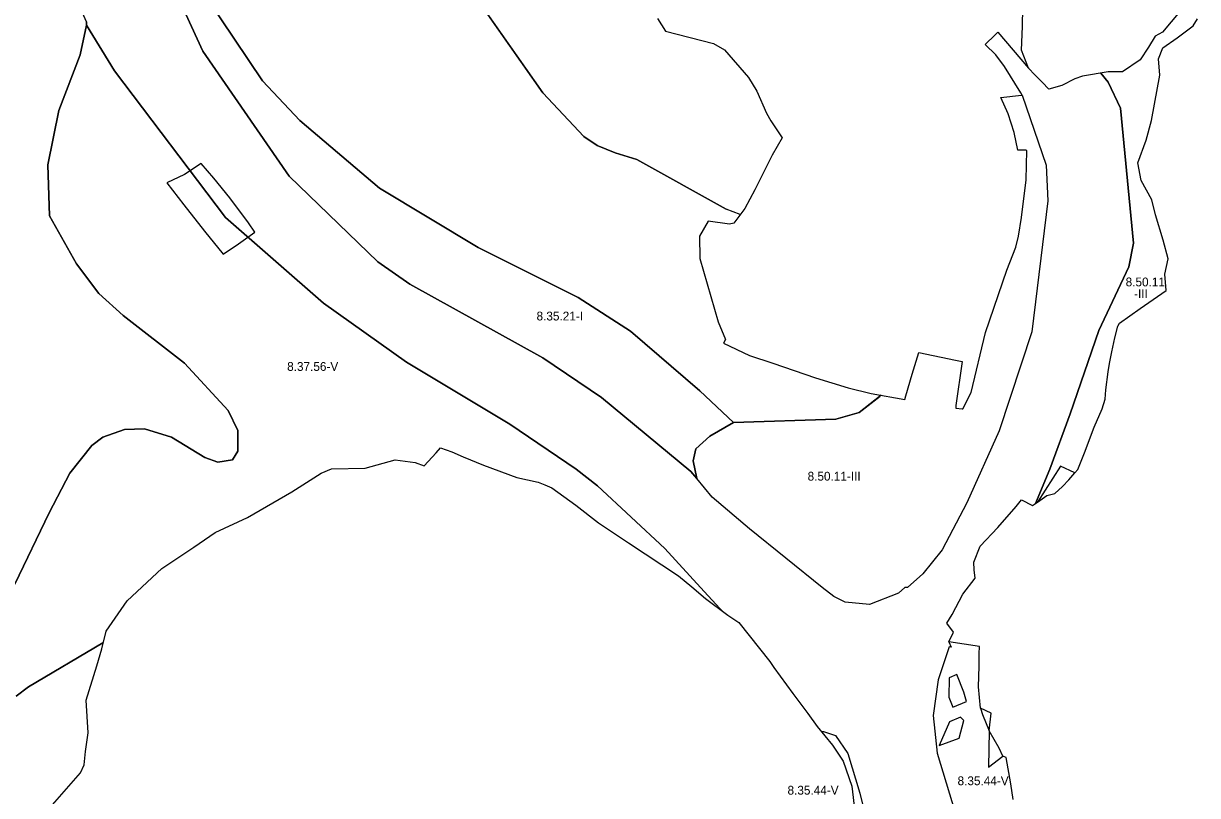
# Model space of a CAD drawing. Extents: x -547623 to -533936, y -1096714 to -1086523.
# Drawn here: x -539983 to -538651, y -1093236 to -1092360 of the extents above; entities that cross this region are included whole.
import ezdxf

# ---------------------------------------------------------------- set-up
doc = ezdxf.new("R2010")
doc.units = 0
for name, color, linetype in [('Vrstva 27', 7, 'Continuous'), ('Vrstva 28', 7, 'Continuous'), ('Vrstva 29', 7, 'Continuous')]:
    doc.layers.add(name, color=color, linetype=linetype)

msp = doc.modelspace()

# ---------------------------------------------------------------- linework, layer by layer
at = {"layer": 'Vrstva 28'}
for p, q in [((-539531, -1092243), (-539393.5, -1092439)), ((-539794.5, -1092302), (-539712, -1092425.5)), ((-539712, -1092425.5), (-539794.5, -1092302)), ((-539779.5, -1092391.5), (-539805.5, -1092335.5)), ((-539911.5, -1092362), (-539919, -1092396)), ((-539919, -1092396), (-539911.5, -1092362)), ((-539911.5, -1092358.5), (-539911.5, -1092362)), ((-539911.5, -1092362), (-539880, -1092414)), ((-539681.5, -1092533.5), (-539779.5, -1092391.5)), ((-539919, -1092396), (-539943, -1092459)), ((-539943, -1092459), (-539919, -1092396)), ((-539880, -1092414), (-539754, -1092580.5)), ((-539712, -1092425.5), (-539669.5, -1092470.5)), ((-539669.5, -1092470.5), (-539712, -1092425.5)), ((-539393.5, -1092439), (-539347, -1092488.5)), ((-538849.5, -1092441.6), (-538822.5, -1092521)), ((-539943, -1092459), (-539955.5, -1092520.5)), ((-539955.5, -1092520.5), (-539943, -1092459)), ((-539669.5, -1092470.5), (-539579, -1092547)), ((-539579, -1092547), (-539669.5, -1092470.5)), ((-539347, -1092488.5), (-539332, -1092498.5)), ((-539332, -1092498.5), (-539311.5, -1092507)), ((-539311.5, -1092507), (-539287, -1092514.5)), ((-539955.5, -1092520.5), (-539953.5, -1092578.5)), ((-539953.5, -1092578.5), (-539955.5, -1092520.5)), ((-539287, -1092514.5), (-539185.5, -1092571)), ((-538822.5, -1092521), (-538820.5, -1092561.5)), ((-539581, -1092630.5), (-539681.5, -1092533.5)), ((-539579, -1092547), (-539467, -1092614.5)), ((-539467, -1092614.5), (-539579, -1092547)), ((-538820.5, -1092561.5), (-538838.5, -1092710)), ((-539953.5, -1092578.5), (-539923, -1092633)), ((-539923, -1092633), (-539953.5, -1092578.5)), ((-539754, -1092580.5), (-539642.5, -1092677.5)), ((-539467, -1092614.5), (-539353.5, -1092671)), ((-539353.5, -1092671), (-539467, -1092614.5)), ((-539923, -1092633), (-539897.5, -1092666.5)), ((-539897.5, -1092666.5), (-539923, -1092633)), ((-539544.5, -1092656), (-539581, -1092630.5)), ((-539393.5, -1092739.5), (-539544.5, -1092656)), ((-539897.5, -1092666.5), (-539870, -1092691.5)), ((-539870, -1092691.5), (-539897.5, -1092666.5)), ((-539353.5, -1092671), (-539294, -1092709.5)), ((-539294, -1092709.5), (-539353.5, -1092671)), ((-539642.5, -1092677.5), (-539548.5, -1092744.5)), ((-539870, -1092691.5), (-539800.5, -1092745.5)), ((-539800.5, -1092745.5), (-539870, -1092691.5)), ((-539294, -1092709.5), (-539215.5, -1092777)), ((-539215.5, -1092777), (-539294, -1092709.5)), ((-538838.5, -1092710), (-538875.5, -1092822.5)), ((-539327, -1092784.5), (-539393.5, -1092739.5)), ((-539800.5, -1092745.5), (-539751, -1092799.5)), ((-539751, -1092799.5), (-539800.5, -1092745.5)), ((-539548.5, -1092744.5), (-539431, -1092815)), ((-539215.5, -1092777), (-539177.1, -1092812.9)), ((-539177.1, -1092812.9), (-539215.5, -1092777)), ((-539225.5, -1092868.5), (-539327, -1092784.5)), ((-539009.5, -1092782), (-539034.5, -1092801.5)), ((-539034.5, -1092801.5), (-539010.9, -1092783.1)), ((-539751, -1092799.5), (-539740, -1092822)), ((-539740, -1092822), (-539751, -1092799.5)), ((-539034.5, -1092801.5), (-539061, -1092809)), ((-539061, -1092809), (-539034.5, -1092801.5)), ((-539431, -1092815), (-539356, -1092866)), ((-539177.1, -1092812.9), (-539204, -1092828.5)), ((-539204, -1092828.5), (-539177.1, -1092812.9)), ((-539061, -1092809), (-539177.1, -1092812.9)), ((-539177.1, -1092812.9), (-539061, -1092809)), ((-539893, -1092829.5), (-539905.5, -1092839)), ((-539905.5, -1092839), (-539893, -1092829.5)), ((-539868.5, -1092821), (-539893, -1092829.5)), ((-539893, -1092829.5), (-539868.5, -1092821)), ((-539846, -1092820), (-539868.5, -1092821)), ((-539868.5, -1092821), (-539846, -1092820)), ((-539815, -1092829.5), (-539846, -1092820)), ((-539846, -1092820), (-539815, -1092829.5)), ((-539777.5, -1092852.5), (-539815, -1092829.5)), ((-539815, -1092829.5), (-539777.5, -1092852.5)), ((-539740, -1092822), (-539740, -1092845.5)), ((-539740, -1092845.5), (-539740, -1092822)), ((-539204, -1092828.5), (-539220, -1092843)), ((-539220, -1092843), (-539204, -1092828.5)), ((-538875.5, -1092822.5), (-538912.5, -1092904)), ((-539905.5, -1092839), (-539930.5, -1092870.5)), ((-539930.5, -1092870.5), (-539905.5, -1092839)), ((-539740, -1092845.5), (-539746, -1092855.5)), ((-539746, -1092855.5), (-539740, -1092845.5)), ((-539220, -1092843), (-539223, -1092856.5)), ((-539223, -1092856.5), (-539220, -1092843)), ((-539762.5, -1092858), (-539777.5, -1092852.5)), ((-539777.5, -1092852.5), (-539762.5, -1092858)), ((-539746, -1092855.5), (-539762.5, -1092858)), ((-539762.5, -1092858), (-539746, -1092855.5)), ((-539223, -1092856.5), (-539219, -1092876.5)), ((-539219, -1092876.5), (-539223, -1092856.5)), ((-539930.5, -1092870.5), (-539954, -1092915.5)), ((-539954, -1092915.5), (-539930.5, -1092870.5)), ((-539356, -1092866), (-539331.5, -1092885)), ((-539219, -1092876.5), (-539225.5, -1092868.5)), ((-539331.5, -1092885), (-539255, -1092956)), ((-539201.5, -1092897.5), (-539219, -1092876.5)), ((-539159, -1092933.5), (-539201.5, -1092897.5)), ((-538912.5, -1092904), (-538940.5, -1092957.5)), ((-539954, -1092915.5), (-539993, -1092996.5)), ((-539993, -1092996.5), (-539954, -1092915.5)), ((-539076.5, -1093000), (-539159, -1092933.5)), ((-539255, -1092956), (-539214.6, -1093000)), ((-538940.5, -1092957.5), (-538962.5, -1092984.5)), ((-538962.5, -1092984.5), (-538979.9, -1093000)), ((-539214.6, -1093000), (-539192.6, -1093024)), ((-539063.5, -1093010.5), (-539076.5, -1093000)), ((-538982.8, -1093000), (-538990, -1093006.5)), ((-538979.9, -1093000), (-538982.8, -1093000)), ((-539050.5, -1093017), (-539063.5, -1093010.5)), ((-539023, -1093019.5), (-539050.5, -1093017)), ((-538990, -1093006.5), (-539023, -1093019.5)), ((-539192.6, -1093024), (-539191.8, -1093024.9)), ((-539191.8, -1093024.9), (-539190.2, -1093026.6)), ((-539977.5, -1093113), (-539893.1, -1093062.9)), ((-539893.1, -1093062.9), (-539977.5, -1093113)), ((-539893.1, -1093062.9), (-539892.7, -1093062.6)), ((-539892.7, -1093062.6), (-539893.1, -1093062.9)), ((-539991.5, -1093123.5), (-539977.5, -1093113)), ((-539977.5, -1093113), (-539991.5, -1093123.5)), ((-539077.6, -1093163.5), (-539077.6, -1093163.5)), ((-539077.6, -1093163.5), (-539077.5, -1093163.5)), ((-539077.5, -1093163.5), (-539077, -1093163.5)), ((-539077, -1093163.5), (-539075, -1093163.5)), ((-539075, -1093163.5), (-539061.5, -1093168)), ((-539061.5, -1093168), (-539047.5, -1093188.5)), ((-539047.5, -1093188.5), (-539034, -1093233.5)), ((-539034, -1093233.5), (-539018, -1093298.5))]:
    msp.add_line(p, q, dxfattribs=at)
for points in [[(-539169.5, -1092577), (-539185.5, -1092571), (-539287, -1092514.5), (-539311.5, -1092507), (-539332, -1092498.5), (-539347, -1092488.5), (-539393.5, -1092439), (-539531, -1092243), (-539596, -1092117.5), (-539651, -1091998.5), (-539660.5, -1091976.5), (-539710, -1091856), (-539731, -1091782), (-539729.5, -1091762), (-539721, -1091717), (-539651, -1091515), (-539633, -1091443), (-539625, -1091372.5), (-539631.5, -1091334.5), (-539656, -1091243.5), (-539657, -1091239.4)], [(-539190.2, -1093026.6), (-539191.8, -1093024.9), (-539192.6, -1093024), (-539214.6, -1093000), (-539255, -1092956), (-539331.5, -1092885), (-539356, -1092866), (-539431, -1092815), (-539548.5, -1092744.5), (-539642.5, -1092677.5), (-539754, -1092580.5), (-539880, -1092414), (-539911.5, -1092362), (-539911.5, -1092358.5), (-539929.5, -1092318), (-539944.5, -1092283.5), (-539956, -1092232.5), (-539974.5, -1092151.5), (-539986, -1092129)], [(-539544.5, -1092656), (-539393.5, -1092739.5), (-539327, -1092784.5), (-539225.5, -1092868.5), (-539219, -1092876.5), (-539223, -1092856.5), (-539220, -1092843), (-539204, -1092828.5), (-539177.1, -1092812.9), (-539215.5, -1092777), (-539294, -1092709.5), (-539353.5, -1092671), (-539467, -1092614.5), (-539579, -1092547), (-539669.5, -1092470.5), (-539712, -1092425.5), (-539794.5, -1092302), (-539828.5, -1092267), (-539831.5, -1092266.5), (-539805.5, -1092335.5), (-539779.5, -1092391.5), (-539681.5, -1092533.5), (-539581, -1092630.5), (-539544.5, -1092656)], [(-538851.2, -1092438.8), (-538869.7, -1092409.2), (-538879.4, -1092395.9), (-538891.4, -1092384), (-538880.2, -1092373.1), (-538877.9, -1092370.8), (-538877.1, -1092370.1), (-538842.4, -1092411.1), (-538850.3, -1092390.5), (-538849.2, -1092363.8), (-538848.7, -1092342.2)], [(-538670.7, -1092346.5), (-538690.2, -1092370.2), (-538698.4, -1092374.6), (-538706.3, -1092387), (-538715.7, -1092401.3), (-538735.7, -1092415.1), (-538751.8, -1092415.1), (-538781.1, -1092419.9), (-538789.8, -1092422.9), (-538804.7, -1092430.7), (-538819.3, -1092434.6), (-538826.9, -1092426.8), (-538835.1, -1092418.4), (-538842.4, -1092411.1), (-538850.3, -1092390.5), (-538849.2, -1092363.8), (-538848.7, -1092342.2)], [(-539930.5, -1092870.5), (-539905.5, -1092839), (-539893, -1092829.5), (-539868.5, -1092821), (-539846, -1092820), (-539815, -1092829.5), (-539777.5, -1092852.5), (-539762.5, -1092858), (-539746, -1092855.5), (-539740, -1092845.5), (-539740, -1092822), (-539751, -1092799.5), (-539800.5, -1092745.5), (-539870, -1092691.5), (-539897.5, -1092666.5), (-539923, -1092633), (-539953.5, -1092578.5), (-539955.5, -1092520.5), (-539943, -1092459), (-539919, -1092396), (-539911.5, -1092362), (-539911.5, -1092358.5)], [(-539263.4, -1092354.6), (-539254.3, -1092368.8), (-539199.9, -1092383), (-539187.6, -1092390.1), (-539160.3, -1092421.4), (-539150.9, -1092437.2), (-539139.7, -1092462.1), (-539134.9, -1092470.6), (-539121.9, -1092489.9), (-539133.4, -1092509.6), (-539152.9, -1092549.1), (-539164.2, -1092570.1), (-539176.9, -1092586.7), (-539181.8, -1092588.1), (-539206.1, -1092584.5), (-539215.9, -1092601.7), (-539215.4, -1092627), (-539194.7, -1092698.7), (-539186.2, -1092718.8), (-539188.6, -1092722.9), (-539159.2, -1092736.8), (-539132.4, -1092745.6), (-539084.2, -1092762.4), (-539047.1, -1092773.6), (-539021, -1092779.9), (-538982.9, -1092786.9), (-538981.7, -1092782.8), (-538974.3, -1092758.3), (-538966.8, -1092733.4), (-538925.2, -1092742.2), (-538917.8, -1092743.8), (-538924.9, -1092793.8), (-538925, -1092796.7), (-538917.8, -1092797.3), (-538916.8, -1092797.4), (-538907.4, -1092779), (-538891.2, -1092710.9), (-538866.9, -1092640.2), (-538856.9, -1092614.2), (-538853.9, -1092601.7), (-538850.4, -1092580.2), (-538845, -1092537.8), (-538844.3, -1092504.2), (-538845.5, -1092503.8), (-538854.5, -1092504), (-538858.6, -1092483.8), (-538865.4, -1092462.8), (-538873.9, -1092444.1), (-538850.2, -1092441.6), (-538849.5, -1092441.6), (-538851.2, -1092438.8)], [(-538859.6, -1093240.8), (-538862.4, -1093222.9), (-538867.9, -1093193), (-538871.4, -1093191.4), (-538875.7, -1093182.6), (-538887.1, -1093162.9), (-538884.8, -1093142.8), (-538896.7, -1093137), (-538899.3, -1093112.9), (-538898.2, -1093089.6), (-538898.2, -1093075.5), (-538898.1, -1093067), (-538932.8, -1093061.8), (-538927.5, -1093050.9), (-538935, -1093040.8), (-538929, -1093030.8), (-538916.9, -1093007.6), (-538903, -1092989.5), (-538903.9, -1092980.2), (-538904.6, -1092971.6), (-538897.2, -1092953.3), (-538877.3, -1092932.2), (-538856.4, -1092908.1), (-538850.2, -1092900.9), (-538838, -1092907.2), (-538832.2, -1092903.2), (-538821.7, -1092895.9), (-538812.3, -1092893.4), (-538803.7, -1092885.6), (-538796.7, -1092877.9), (-538789.6, -1092870), (-538786.3, -1092866.3), (-538778.9, -1092847.2), (-538768, -1092818.1), (-538758.9, -1092797.3), (-538755.2, -1092786.5), (-538754.5, -1092776), (-538751.9, -1092755.4), (-538750.5, -1092746.2), (-538747.9, -1092732.9), (-538744.3, -1092716.9), (-538740.9, -1092703.8), (-538739.2, -1092700.3), (-538715.8, -1092683.7), (-538686.2, -1092663.2), (-538687.7, -1092644.8), (-538683.7, -1092627.1), (-538689.4, -1092606), (-538698.3, -1092577.3), (-538702.3, -1092560.5), (-538714.6, -1092538.5), (-538718.4, -1092518.5), (-538708.9, -1092492.8), (-538702.7, -1092470.4), (-538699.2, -1092451.7), (-538693.2, -1092419), (-538694.9, -1092400.3), (-538689.9, -1092388), (-538673.7, -1092376.6), (-538655.5, -1092362.9), (-538650.5, -1092355.1)], [(-538834.3, -1092904.7), (-538818, -1092866), (-538795, -1092803), (-538762.5, -1092708.5), (-538728.5, -1092636.5), (-538723, -1092609.5), (-538738, -1092456.5), (-538752, -1092427), (-538760.3, -1092416.5)], [(-538760.3, -1092416.5), (-538752, -1092427), (-538738, -1092456.5), (-538723, -1092609.5), (-538728.5, -1092636.5), (-538762.5, -1092708.5), (-538795, -1092803), (-538818, -1092866), (-538834.3, -1092904.7)], [(-539950.1, -1093246.8), (-539918.3, -1093210.6), (-539914.4, -1093201.4), (-539912.9, -1093186.3), (-539909.7, -1093165.2), (-539912.2, -1093128), (-539900, -1093088.9), (-539894.4, -1093069.7), (-539889.5, -1093049.8), (-539865.5, -1093015.4), (-539826.3, -1092978.7), (-539789.8, -1092954.6), (-539765.6, -1092937.8), (-539729, -1092920.6), (-539678.4, -1092891.6), (-539645.2, -1092870.5), (-539633.7, -1092865.4), (-539595.5, -1092864.8), (-539561.1, -1092855.3), (-539538.6, -1092858.4), (-539528.4, -1092862.1), (-539514.8, -1092847.2), (-539510, -1092841.9), (-539497, -1092846.4), (-539483.9, -1092852.1), (-539460.9, -1092861.2), (-539423.2, -1092875.2), (-539398.9, -1092880.7), (-539391.3, -1092883.8), (-539383.3, -1092887), (-539356.1, -1092906.6), (-539330.4, -1092926.8), (-539296.6, -1092949.6), (-539239.8, -1092987), (-539224.6, -1092999.6), (-539209, -1093012.5), (-539183.7, -1093031.6), (-539171.3, -1093040), (-539159.3, -1093054.5), (-539136, -1093084.3), (-539131.5, -1093090.8), (-539109.7, -1093120.6), (-539093, -1093143), (-539082.1, -1093158), (-539064.8, -1093179.1), (-539052.7, -1093197.2), (-539043, -1093225.6), (-539039.5, -1093254.9)], [(-539993, -1092996.5), (-539954, -1092915.5), (-539930.5, -1092870.5)], [(-538806.1, -1092862.6), (-538832.2, -1092903.2), (-538821.7, -1092895.9), (-538812.3, -1092893.4), (-538803.7, -1092885.6), (-538796.7, -1092877.9), (-538789.6, -1092870), (-538806.1, -1092862.6)], [(-538932.8, -1093061.8), (-538930, -1093068), (-538932.5, -1093067.5), (-538945, -1093105), (-538950.5, -1093145.5), (-538946, -1093188), (-538925.5, -1093255.5), (-538903, -1093306.8), (-538902.1, -1093308.8)], [(-538928.3, -1093136.1), (-538912.7, -1093129.4), (-538915.7, -1093118.9), (-538923.8, -1093098.8), (-538932.3, -1093102.5), (-538932.9, -1093124.6), (-538928.3, -1093136.1)], [(-538887.1, -1093162.9), (-538884.8, -1093142.8), (-538896.7, -1093137), (-538894.6, -1093144.1), (-538887.1, -1093162.9)], [(-538943.8, -1093179.6), (-538921.1, -1093171.2), (-538915.6, -1093151.1), (-538919.5, -1093147.2), (-538932.1, -1093152.7), (-538943.8, -1093179.6)], [(-538887.6, -1093203.9), (-538871.4, -1093191.4), (-538875.7, -1093182.6), (-538887.1, -1093162.9), (-538887.6, -1093203.9)]]:
    msp.add_lwpolyline(points, dxfattribs=at)
at = {"layer": 'Vrstva 29'}
msp.add_lwpolyline([(-539739.3, -1092610.2), (-539720.7, -1092597.1), (-539727.7, -1092586.3), (-539748.9, -1092557.9), (-539767.2, -1092535.9), (-539781.5, -1092519.2), (-539800.3, -1092531.5), (-539820.3, -1092541.1), (-539801, -1092566), (-539777.6, -1092596), (-539756.7, -1092621.8), (-539739.3, -1092610.2)], dxfattribs=at)

# ---------------------------------------------------------------- texts
at = {"layer": 'Vrstva 27'}
for s, p in [('8.50.11', (-538732.1, -1092658.5)), ('-III', (-538722.5, -1092671.8)), ('8.35.21-I', (-539400.8, -1092697.2)), ('8.37.56-V', (-539683.9, -1092754.4)), ('8.50.11-III', (-539093.1, -1092878.9)), ('8.35.44-V', (-538922.9, -1093224.5)), ('8.35.44-V', (-539115.9, -1093235.2))]:
    msp.add_text(s, height=10, dxfattribs=at).set_placement(p)

doc.saveas('drawing.dxf')
